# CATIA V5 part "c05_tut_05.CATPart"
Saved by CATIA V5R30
Part number: Part1
Bounding box of the stored display mesh (mm): x -12 to 12, y 0 to 257, z -11.99 to 11.99
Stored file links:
  D:\CADCIM\CATIA\2020\Ch5\c05\c05_tut_05.CATPart
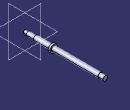
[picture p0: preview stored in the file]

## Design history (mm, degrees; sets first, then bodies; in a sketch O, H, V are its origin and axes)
Body1 (main body)
  Sketch1 on zx-plane, origin (0, 0, 0), H (-1, 0, 0), V (0, 0, 1)
    circle A1 centre (0, 0) radius 5
    circle A2 centre (0, 0) radius 6.5
    circle A3 centre (0, 0) radius 8
    circle A4 centre (0, 0) radius 7
    circle A5 centre (0, 0) radius 12
    radius A1 = 5
    radius A2 = 6.5
    radius A3 = 8
    radius A4 = 7
    radius A5 = 12
  MultiPad1: profile Sketch1, domains (length 93 / length -87; length 257 / length -35; length 241 / length -35; length 257 / length -11; length 257)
